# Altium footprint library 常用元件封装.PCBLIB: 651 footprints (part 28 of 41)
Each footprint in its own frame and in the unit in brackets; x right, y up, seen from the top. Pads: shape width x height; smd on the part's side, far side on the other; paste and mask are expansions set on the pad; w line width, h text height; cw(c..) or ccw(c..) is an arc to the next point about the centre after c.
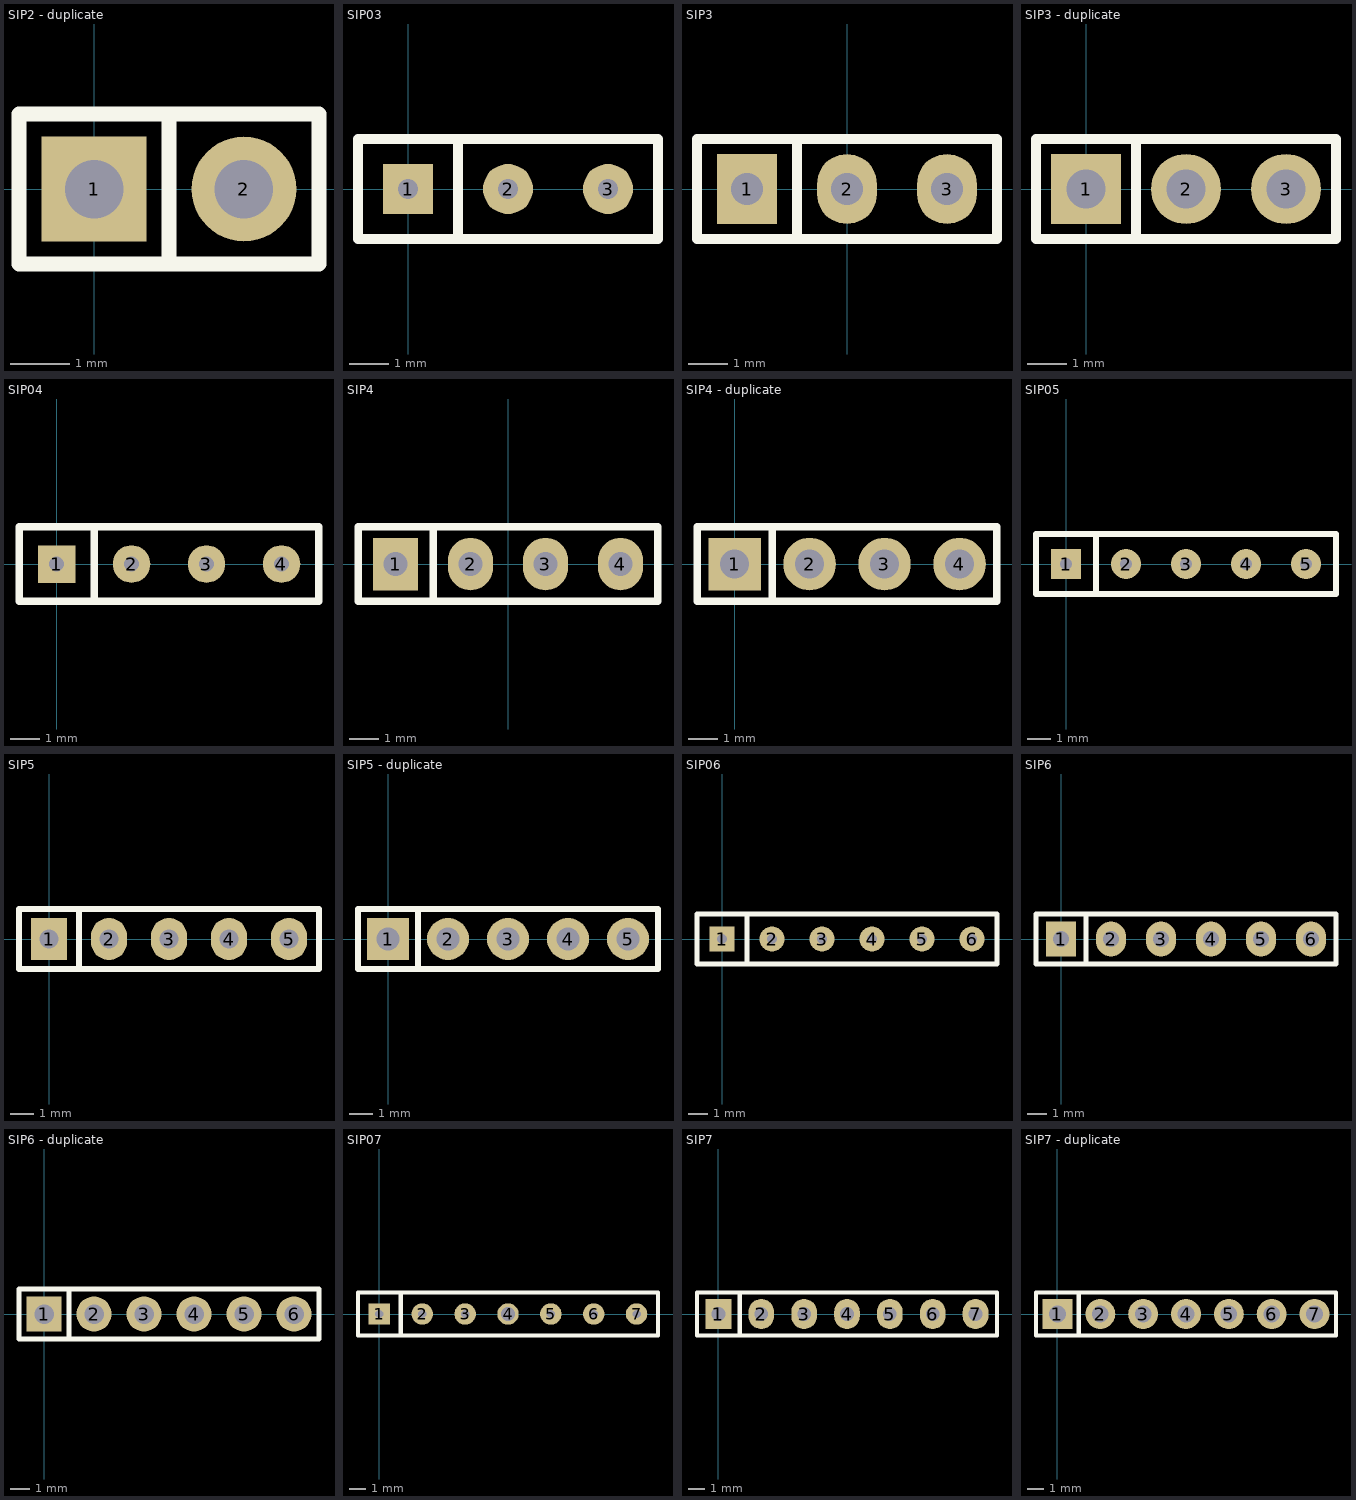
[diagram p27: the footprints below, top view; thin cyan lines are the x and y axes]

## SIP2 - duplicate [mil]
pads (2):
  rect 70x70 hole 39: 1(0,0)
  round 70 hole 39: 2(100,0)
TopOverlay:
  lines w10: 50,-50 50,50 ; -50,-50 -50,50 150,50 150,-50 -50,-50

## SIP03 [mm]
pads (3):
  rect 1.27x1.27 hole 0.5: 1(0,0)
  round 1.27 hole 0.5: 2(2.54,0) 3(5.08,0)
TopOverlay:
  lines w0.254: 1.27,-1.27 1.27,1.27 ; -1.27,-1.27 -1.27,1.27 6.35,1.27 6.35,-1.27 -1.27,-1.27

## SIP3 [mil]
pads (3):
  rect 60x70 hole 32: 1(-100,0)
  oval 60x70 hole 32: 2(0,0) 3(100,0)
TopOverlay:
  lines w10: -50,-50 -50,50 ; -150,-50 150,-50 150,50 -150,50 -150,-50

## SIP3 - duplicate [mil]
pads (3):
  rect 70x70 hole 39: 1(0,0)
  round 70 hole 39: 2(100,0) 3(200,0)
TopOverlay:
  lines w10: 50,-50 50,50 ; -50,-50 -50,50 250,50 250,-50 -50,-50

## SIP04 [mm]
pads (4):
  rect 1.27x1.27 hole 0.5: 1(0,0)
  round 1.27 hole 0.5: 2(2.54,0) 3(5.08,0) 4(7.62,0)
TopOverlay:
  lines w0.254: 1.27,-1.27 1.27,1.27 ; -1.27,-1.27 -1.27,1.27 8.89,1.27 8.89,-1.27 -1.27,-1.27

## SIP4 [mil]
pads (4):
  rect 60x70 hole 32: 1(-150,0)
  oval 60x70 hole 32: 2(-50,0) 3(50,0) 4(150,0)
TopOverlay:
  lines w10: -100,-50 -100,50 ; -200,-50 200,-50 200,50 -200,50 -200,-50

## SIP4 - duplicate [mil]
pads (4):
  rect 70x70 hole 39: 1(0,0)
  round 70 hole 39: 2(100,0) 3(200,0) 4(300,0)
TopOverlay:
  lines w10: 50,-50 50,50 ; -50,-50 350,-50 350,50 -50,50 -50,-50

## SIP05 [mm]
pads (5):
  rect 1.27x1.27 hole 0.5: 1(0,0)
  round 1.27 hole 0.5: 2(2.54,0) 3(5.08,0) 4(7.62,0) 5(10.16,0)
TopOverlay:
  lines w0.254: 1.27,-1.27 1.27,1.27 ; -1.27,-1.27 11.43,-1.27 11.43,1.27 -1.27,1.27 -1.27,-1.27

## SIP5 [mil]
pads (5):
  rect 60x70 hole 32: 1(0,0)
  oval 60x70 hole 32: 2(100,0) 3(200,0) 4(300,0) 5(400,0)
TopOverlay:
  lines w10: 50,-50 50,50 ; -50,-50 -50,50 450,50 450,-50 -50,-50

## SIP5 - duplicate [mil]
pads (5):
  rect 70x70 hole 39: 1(0,0)
  round 70 hole 39: 2(100,0) 3(200,0) 4(300,0) 5(400,0)
TopOverlay:
  lines w10: 50,-50 50,50 ; -50,-50 -50,50 450,50 450,-50 -50,-50

## SIP06 [mm]
pads (6):
  rect 1.27x1.27 hole 0.5: 1(0,0)
  round 1.27 hole 0.5: 2(2.54,0) 3(5.08,0) 4(7.62,0) 5(10.16,0) 6(12.7,0)
TopOverlay:
  lines w0.254: 1.27,-1.27 1.27,1.27 ; -1.27,-1.27 13.97,-1.27 13.97,1.27 -1.27,1.27 -1.27,-1.27

## SIP6 [mil]
pads (6):
  rect 60x70 hole 32: 1(0,0)
  oval 60x70 hole 32: 2(100,0) 3(200,0) 4(300,0) 5(400,0) 6(500,0)
TopOverlay:
  lines w10: 50,-50 50,50 ; -50,-50 -50,50 550,50 550,-50 -50,-50

## SIP6 - duplicate [mil]
pads (6):
  rect 70x70 hole 39: 1(0,0)
  round 70 hole 39: 2(100,0) 3(200,0) 4(300,0) 5(400,0) 6(500,0)
TopOverlay:
  lines w10: 50,-50 50,50 ; -50,-50 550,-50 550,50 -50,50 -50,-50

## SIP07 [mm]
pads (7):
  rect 1.27x1.27 hole 0.5: 1(0,0)
  round 1.27 hole 0.5: 2(2.54,0) 3(5.08,0) 5(10.16,0) 6(12.7,0) 7(15.24,0)
  round 1.27 hole 0.813: 4(7.62,0)
TopOverlay:
  lines w0.254: 1.27,-1.27 1.27,1.27 ; -1.27,-1.27 -1.27,1.27 16.51,1.27 16.51,-1.27 -1.27,-1.27

## SIP7 [mil]
pads (7):
  rect 60x70 hole 32: 1(0,0)
  oval 60x70 hole 32: 2(100,0) 3(200,0) 4(300,0) 5(400,0) 6(500,0) 7(600,0)
TopOverlay:
  lines w10: 50,-50 50,50 ; -50,-50 650,-50 650,50 -50,50 -50,-50

## SIP7 - duplicate [mil]
pads (7):
  rect 70x70 hole 39: 1(0,0)
  round 70 hole 39: 2(100,0) 3(200,0) 4(300,0) 5(400,0) 6(500,0) 7(600,0)
TopOverlay:
  lines w10: 50,-50 50,50 ; -50,-50 -50,50 650,50 650,-50 -50,-50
